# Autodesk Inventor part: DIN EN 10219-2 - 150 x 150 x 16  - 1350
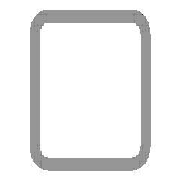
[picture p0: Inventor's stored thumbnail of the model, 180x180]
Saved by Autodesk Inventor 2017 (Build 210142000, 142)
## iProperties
_CCFamilyMember: 76
_CCFamilyDisplayName: DIN EN 10219-2 (Square Hollow Section - Cold Formed) - Cold formed welded structural hollow sections of non-alloy and fine grain structural steel
_FrameMemberDoc: Frame Member File
_Version: 15.0.0
_GetPNFromCC: 1
Created: 2017-11
Part Number: DIN EN 10219-2 - 150 x 150 x 16  - 1350
Material: Steel, Mild
Description: Cold formed welded structural hollow sections of non-alloy and fine grain structural steel
Document SubType Name: Modeling
Standard: DIN
Designer: iusti
Standard Revision: 2006-07
Standards Organization: DIN
Language: en-US
Size Designation: 150 x 150 x 16
Categories: <MemberInstance><Categories><Category DisplayName="Structural Shapes" InternalName="089c4875-fa83-4c05-b084-43b9cc11f5ed" Mnemonic="GRDR"><CategoryParameter Dis
Stock Number: 150 x 150 x 16
Mass: 79240 g
Surface Area: 12767.4 cm^2
Volume: 10094.3 cm^3
Density: 7.85 g/cm^3
Appearance: Semi-Polished
IsCustomPart: 1
G_L: 1350.000 mm
G_W: 150.000 mm
G_H: 150.000 mm
+6A2F0504-0522-4D64-B7B8-70050364F92E+CUTDETAIL1: Cut
+3EEB6A9D-7D4A-469C-884C-F4929F57B2CA+CUTDETAIL2: Cut
Author: iusti
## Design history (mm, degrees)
node "Start plane"
node "End plane"
sketch "Sketch"
  geometry: L1 (-75, -27)-(-75, 27); L2 (-27, 75)-(27, 75); L3 (75, 27)-(75, -27); L4 (27, -75)-(-27, -75); L5 (-27, 59)-(27, 59); L6 (59, 27)-(59, -27); L7 (27, -59)-(-27, -59); L8 (-59, -27)-(-59, 27); L9 (0, 118.918)-(0, -118.918) reference; L10 (-118.918, 0)-(118.918, 0) reference; A1 r 48 centre (-27, -27) between (-75, -27) and (-27, -75); A2 r 48 centre (-27, 27) between (-27, 75) and (-75, 27); A3 r 48 centre (27, 27) between (75, 27) and (27, 75); A4 r 48 centre (27, -27) between (27, -75) and (75, -27); A5 r 32 centre (-27, 27) between (-27, 59) and (-59, 27); A6 r 32 centre (27, 27) between (59, 27) and (27, 59); A7 r 32 centre (27, -27) between (27, -59) and (59, -27); A8 r 32 centre (-27, -27) between (-59, -27) and (-27, -59)
  constraints: 16 end point, 16 point on circle, 8 centre point, 8 tangent, 4 parallel, 3 equal radius, 2 perpendicular, 7 other
  dimensions: "d7" = 48 radius of A1 (= G_IR); "d10" = 150 distance between parallel lines of L2 L4 (= G_H); "d11" = 150 distance between parallel lines of L1 L3 (= G_W); "d12" = 16 distance between parallel lines of L3 L6 (= G_T); "d15" = 75 distance between parallel lines of L2 L10 (= 0.5 x d10); "d16" = 75 distance between parallel lines of L9 L3 (= 0.5 x d11)
extrude "Body" new body sketch "Sketch" stored distance "d3" = 1350 (= G_L); taper "d4" = 0 deg
node "Driven Length"
  sketch "Sketch3"
    geometry: L1 (0, 0)-(10, 0) reference
    constraints: 2 end point, 1 horizontal
  workplane "Work Plane3"
  sketch "Sketch4"
    geometry: L1 (-2, 75)-(12, 75) reference; L2 (-2, 1425)-(12, 1425) reference
    dimensions: "d18" = 1350 distance between parallel lines of L1 L2 (derived)
workplane "Work Plane4"
split "Split1"
workplane "Work Plane5"
split "Split2"
body "Solid1"
other parameters: "G_W" = 150 [user parameter; used in 1 equation term], "G_H" = 150 [user parameter; used in 1 equation term], "G_T" = 16 [user parameter; used in 1 equation term], "G_IR" = 48 [user parameter; used in 1 equation term], "G_L" = 1350 (= d18) [user parameter; used in 1 equation term], "G_OFFSET_START" = -75 [user parameter; used in 1 equation term], "G_OFFSET_END" = -75 [user parameter; used in 1 equation term], "d13" = 75 (= -G_OFFSET_START), "d14" = 1425 (= G_OFFSET_END + B_L), "d17" = 90 deg
